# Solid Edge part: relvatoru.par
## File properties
Author: Georg
Template: Iso Metric Part.par
Last saved by: Georg
Revision: 7
Application: Solid Edge
Accuracy: 0,990
Face Style: Model Default
Fill Style: Normal
Coef. of Thermal Exp: 0.0
Thermal Conductivity: 0.0
Specific Heat: 0.0
Modulus of Elasticity: 0.0
Poisson's Ratio: 0.0
Yield Stress: 0.0
Ultimate Stress: 0.0
Elongation: 0.0
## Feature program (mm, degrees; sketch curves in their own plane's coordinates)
sketch for "ExtrudedProtrusion_1" plane through (0, 4350, 0) normal (0, -1, 0) x-axis (1, 0, 0)
  circle centre (0, -620) radius 10
extrude "ExtrudedProtrusion_1" add finite 20 along +normal
sketch for "ExtrudedProtrusion_2" plane through (0, 4330, -620) normal (0, -1, 0) x-axis (0, 0, -1)
  circle centre (0, 0) radius 75
extrude "ExtrudedProtrusion_2" add finite 20 along +normal
sketch for "ExtrudedProtrusion_3" plane through (0, 4310, -620) normal (0, -1, 0) x-axis (-1, 0, 0)
  circle centre (0, -42.2857) radius 22.5
extrude "ExtrudedProtrusion_3" add finite 650 along +normal
sketch for "ExtrudedCutout_1" plane through (0, 3660, -577.7143) normal (0, -1, 0) x-axis (1, 0, 0)
  circle centre (0, 0) radius 15
extrude "ExtrudedCutout_1" cut finite 600 along -normal
sketch for "ExtrudedProtrusion_4" plane through (0, 3660, -577.7143) normal (0, -1, 0) x-axis (1, 0, 0)
  circle centre (0, 0) radius 22.5
extrude "ExtrudedProtrusion_4" add finite 10 along +normal
sketch for "ExtrudedCutout_2" plane through (0, 3650, -577.7143) normal (0, -1, 0) x-axis (1, 0, 0)
  circle centre (0, 0) radius 20
extrude "ExtrudedCutout_2" cut finite 10 along -normal
sketch for "ExtrudedCutout_3" #1 plane through (0, 0, 0) normal (1, 0, 0) x-axis (0, 1, 0)
  circle centre (3944.523, -577.7143) radius 10
sketch for "ExtrudedCutout_3" #2 plane through (0, 0, 0) normal (1, 0, 0) x-axis (0, 1, 0)
  circle centre (3744.523, -577.7143) radius 10
sketch for "ExtrudedCutout_3" #3 plane through (0, 0, 0) normal (1, 0, 0) x-axis (0, 1, 0)
  circle centre (3794.523, -577.7143) radius 10
sketch for "ExtrudedCutout_3" #4 plane through (0, 0, 0) normal (1, 0, 0) x-axis (0, 1, 0)
  circle centre (3844.523, -577.7143) radius 10
sketch for "ExtrudedCutout_3" #5 plane through (0, 0, 0) normal (1, 0, 0) x-axis (0, 1, 0)
  circle centre (3894.523, -577.7143) radius 10
extrude "ExtrudedCutout_3" cut finite 38.5225 along +normal
pattern "unnamed Pattern 1" of "ExtrudedCutout_3"
extrude "unnamed Cutout 1" cut finite 38.5225
extrude "unnamed Cutout 2" cut finite 38.5225
pattern "Pattern_6" of "ExtrudedProtrusion_3", "ExtrudedCutout_1", "ExtrudedProtrusion_4", "ExtrudedCutout_2", "ExtrudedCutout_3", "unnamed Pattern 1" along a curve  XDirCount = 5; XDirSpacing = 94.2478 mm
extrude "unnamed Protrusion 1" add finite 650
extrude "unnamed Cutout 3" cut finite 600
extrude "unnamed Protrusion 2" add finite 10
extrude "unnamed Cutout 4" cut finite 10
extrude "unnamed Cutout 5" cut finite 38.5225
extrude "unnamed Cutout 6" cut finite 38.5225
extrude "unnamed Cutout 7" cut finite 38.5225
extrude "unnamed Protrusion 3" add finite 650
extrude "unnamed Cutout 8" cut finite 600
extrude "unnamed Protrusion 4" add finite 10
extrude "unnamed Cutout 9" cut finite 10
extrude "unnamed Cutout 10" cut finite 38.5225
extrude "unnamed Cutout 11" cut finite 38.5225
extrude "unnamed Cutout 12" cut finite 38.5225
extrude "unnamed Protrusion 5" add finite 650
extrude "unnamed Cutout 13" cut finite 600
extrude "unnamed Protrusion 6" add finite 10
extrude "unnamed Cutout 14" cut finite 10
extrude "unnamed Cutout 15" cut finite 38.5225
extrude "unnamed Cutout 16" cut finite 38.5225
extrude "unnamed Cutout 17" cut finite 38.5225
extrude "unnamed Protrusion 7" add finite 650
extrude "unnamed Cutout 18" cut finite 600
extrude "unnamed Protrusion 8" add finite 10
extrude "unnamed Cutout 19" cut finite 10
extrude "unnamed Cutout 20" cut finite 38.5225
extrude "unnamed Cutout 21" cut finite 38.5225
extrude "unnamed Cutout 22" cut finite 38.5225
sketch for "ExtrudedProtrusion_21" #1 plane through (0, 3705, -620) normal (0, -1, 0) x-axis (1, 0, 0)
  circle centre (0, 0) radius 75
sketch for "ExtrudedProtrusion_21" #2 plane through (0, 3705, -620) normal (0, -1, 0) x-axis (1, 0, 0)
  circle centre (-40.2161, 13.0671) radius 15
sketch for "ExtrudedProtrusion_21" #3 plane through (0, 3705, -620) normal (0, -1, 0) x-axis (1, 0, 0)
  circle centre (0, 42.2857) radius 15
sketch for "ExtrudedProtrusion_21" #4 plane through (0, 3705, -620) normal (0, -1, 0) x-axis (1, 0, 0)
  circle centre (40.2161, 13.0671) radius 15
sketch for "ExtrudedProtrusion_21" #5 plane through (0, 3705, -620) normal (0, -1, 0) x-axis (1, 0, 0)
  circle centre (24.8548, -34.2099) radius 15
sketch for "ExtrudedProtrusion_21" #6 plane through (0, 3705, -620) normal (0, -1, 0) x-axis (1, 0, 0)
  circle centre (-24.8548, -34.2099) radius 15
extrude "ExtrudedProtrusion_21" add finite 5 symmetric
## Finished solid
Body 1: solid body, 168 faces, 331 edges, 90 vertices.
  Faces by surface: cylinder 123, plane 45
  Edges by curve: intersection 195, circle 91, line 45
Bounding box of the edges (mm): 150.000 x 700.000 x 150.000, from (-75, 3650, -695) to (75, 4350, -545).
Cylindrical faces by radius (mm): R10 x101, R15 x5, R20 x5, R22.5 x10, R75 x2
Planar faces by outward normal: +y 3, -y 17, oblique 25
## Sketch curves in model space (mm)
circle centre (0, 4350, -620) radius 10
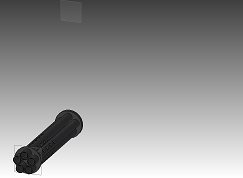
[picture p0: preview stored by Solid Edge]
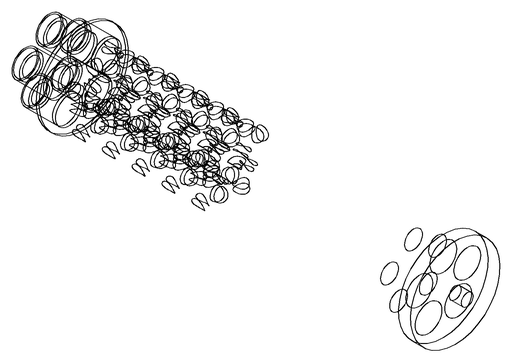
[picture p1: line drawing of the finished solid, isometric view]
